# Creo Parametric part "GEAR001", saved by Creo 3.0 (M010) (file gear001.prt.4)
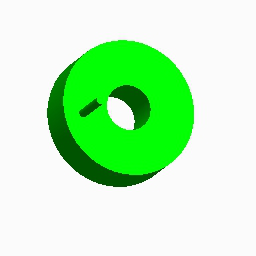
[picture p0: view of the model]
Units: millimeter Newton Second (mmNs); MM, TONNE, SECS

Created from: INLBS_PART_SOLID.PRT

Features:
  1. datum plane "RIGHT"
  2. datum plane "TOP"
  3. datum plane "FRONT"
  4. coordinate system
  5. extrusion "Extrude 1"
  6. extrusion "Extrude 2"

Surfaces: 6 plane, 6 cylinder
